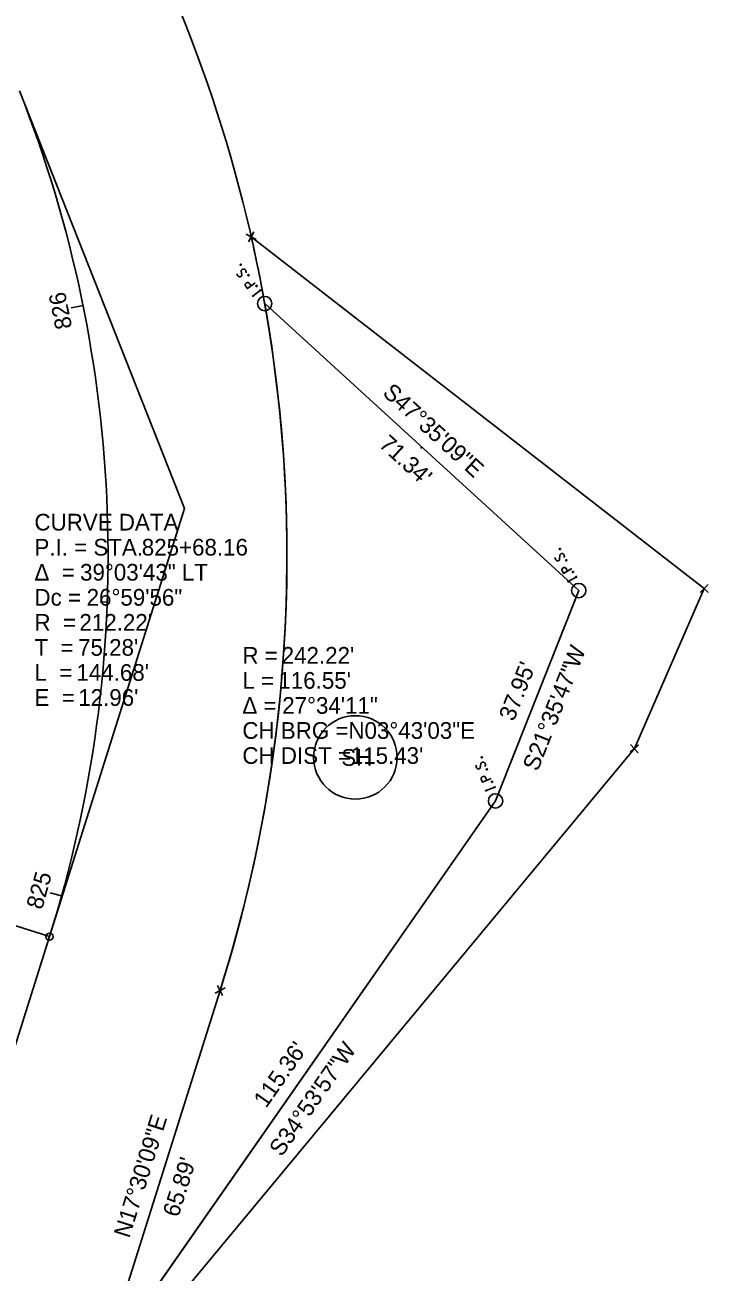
# Model space of a CAD drawing. Extents: x 2376935 to 2379466, y 252990 to 254108.
# Drawn here: x 2378019.8 to 2378134.4, y 253579.4 to 253788.5 of the extents above; entities that cross this region are included whole.
import ezdxf

# ---------------------------------------------------------------- set-up
doc = ezdxf.new("R2010")
doc.units = 0
for name, color, linetype in [('_CIVIL_CONSTRUCTION', 7, 'Continuous'), ('CM_Corridor_Key_Station', 7, 'Continuous'), ('MD_P_Special_Benching_CheckPoint', 7, 'Continuous'), ('PF_X_Ground_Line', 7, 'Continuous'), ('PV_P_Joint', 7, 'Continuous'), ('SC_Scratch1', 7, 'Continuous'), ('SC_Scratch11', 7, 'Continuous'), ('SH_Border', 7, 'Continuous'), ('SH_Cut_Line', 7, 'Continuous'), ('SH_Data', 7, 'Continuous'), ('UT_X_Electric', 7, 'Continuous'), ('UT_X_FO', 7, 'Continuous'), ('UT_X_Misc_Cells', 7, 'Continuous'), ('VG_P_Cells', 7, 'Continuous')]:
    doc.layers.add(name, color=color, linetype=linetype)

msp = doc.modelspace()

# ---------------------------------------------------------------- linework, layer by layer
at = {"layer": '_CIVIL_CONSTRUCTION'}
for p, q in [((2378029.53, 253741.45), (2378027.57, 253741.06)), ((2378033.59, 253691.73), (2378032.39, 253691.78)), ((2378025.93, 253642.44), (2378024.01, 253642.98))]:
    msp.add_line(p, q, dxfattribs=at)
at = {"layer": 'CM_Corridor_Key_Station'}
msp.add_circle((2378075.21, 253665.67), 7, dxfattribs=at)
at = {"layer": 'MD_P_Special_Benching_CheckPoint'}
for p, q in [((2378057.74, 253752.97), (2378133.68, 253693.98)), ((2378112.67, 253693.66), (2378060, 253741.78)), ((2378098.71, 253658.38), (2378112.67, 253693.66)), ((2378133.68, 253693.98), (2378122, 253667.16)), ((2378122, 253667.16), (2378030.6, 253557.09)), ((2378032.7, 253563.76), (2378098.71, 253658.38))]:
    msp.add_line(p, q, dxfattribs=at)
msp.add_arc((2377821.51, 253699.44), 242.22, 10.0673, 12.7672, dxfattribs=at)
at = {"layer": 'PF_X_Ground_Line'}
for p, q in [((2378046.78, 253788.45), (2377965.62, 253993.88)), ((2377963.22, 253343.41), (2378052.52, 253626.6))]:
    msp.add_line(p, q, dxfattribs=at)
msp.add_arc((2377821.51, 253699.44), 242.22, 342.4977, 21.5597, dxfattribs=at)
at = {"layer": 'SC_Scratch1'}
msp.add_line((2378023.91, 253635.62), (2377980.99, 253649.15), dxfattribs=at)
msp.add_circle((2378023.91, 253635.62), 0.6, dxfattribs=at)
at = {"layer": 'SC_Scratch11'}
for p, q in [((2378060, 253741.78), (2378112.67, 253693.66)), ((2378112.67, 253693.66), (2378098.71, 253658.38)), ((2378098.71, 253658.38), (2378032.7, 253563.76)), ((2378032.7, 253563.76), (2378052.52, 253626.6))]:
    msp.add_line(p, q, dxfattribs=at)
msp.add_arc((2377821.51, 253699.44), 242.22, 342.4977, 10.0673, dxfattribs=at)
at = {"layer": 'SH_Border'}
for p, q in [((2378058.57, 253752.53), (2378056.91, 253753.41)), ((2378057.3, 253752.14), (2378058.19, 253753.8)), ((2378134.35, 253693.32), (2378133.01, 253694.64)), ((2378133.02, 253693.31), (2378134.35, 253694.65)), ((2378121.3, 253666.53), (2378122.7, 253667.79)), ((2378122.64, 253666.46), (2378121.37, 253667.86)), ((2378051.68, 253626.16), (2378053.35, 253627.03)), ((2378052.95, 253625.76), (2378052.08, 253627.43))]:
    msp.add_line(p, q, dxfattribs=at)
at = {"layer": 'SH_Cut_Line'}
for points in [[(2378055.9, 253748.19), (2378055.87, 253748.24), (2378055.87, 253748.28), (2378055.89, 253748.33), (2378055.94, 253748.37), (2378056, 253748.38), (2378056.04, 253748.37), (2378056.07, 253748.32), (2378056.07, 253748.28), (2378056.05, 253748.22), (2378056, 253748.19), (2378055.94, 253748.18), (2378055.9, 253748.19)], [(2378055.38, 253746.78), (2378055.37, 253746.74), (2378055.37, 253746.7), (2378055.4, 253746.6), (2378055.45, 253746.49), (2378055.51, 253746.42), (2378055.53, 253746.39), (2378055.64, 253746.3), (2378055.78, 253746.25), (2378055.9, 253746.25), (2378056, 253746.29), (2378056.06, 253746.33), (2378056.12, 253746.41), (2378056.14, 253746.54), (2378056.08, 253747.25), (2378056.08, 253747.32), (2378056.11, 253747.37), (2378056.16, 253747.43), (2378056.22, 253747.48), (2378056.29, 253747.52), (2378056.33, 253747.54), (2378056.4, 253747.56), (2378056.45, 253747.57), (2378056.49, 253747.58), (2378056.54, 253747.57), (2378056.58, 253747.56), (2378056.63, 253747.54), (2378056.66, 253747.52), (2378056.73, 253747.45), (2378056.82, 253747.33), (2378056.86, 253747.23), (2378056.88, 253747.06), (2378056.87, 253746.95)], [(2378057.22, 253746.45), (2378057.18, 253746.49), (2378057.18, 253746.54), (2378057.2, 253746.59), (2378057.25, 253746.63), (2378057.31, 253746.63), (2378057.35, 253746.62), (2378057.39, 253746.58), (2378057.39, 253746.54), (2378057.37, 253746.48), (2378057.32, 253746.44), (2378057.26, 253746.44), (2378057.22, 253746.45)], [(2378058.38, 253745.27), (2378057.1, 253744.3), (2378056.78, 253744.73), (2378056.76, 253744.78), (2378056.73, 253744.85), (2378056.73, 253744.9), (2378056.73, 253744.94), (2378056.75, 253745.01), (2378056.78, 253745.08), (2378056.85, 253745.15), (2378056.97, 253745.24), (2378057.02, 253745.27), (2378057.09, 253745.29), (2378057.19, 253745.31), (2378057.25, 253745.3), (2378057.29, 253745.29), (2378057.34, 253745.26), (2378057.4, 253745.2), (2378057.72, 253744.77)], [(2378059.32, 253744.02), (2378058.04, 253743.05)], [(2378058.57, 253744.65), (2378058.54, 253744.7), (2378058.54, 253744.74), (2378058.56, 253744.8), (2378058.61, 253744.83), (2378058.67, 253744.84), (2378058.71, 253744.83), (2378058.74, 253744.78), (2378058.74, 253744.74), (2378058.72, 253744.68), (2378058.67, 253744.65), (2378058.61, 253744.64), (2378058.57, 253744.65)], [(2378059.42, 253743.88), (2378059.21, 253744.16)], [(2378058.15, 253742.91), (2378057.93, 253743.19)], [(2378108.73, 253699.21), (2378108.72, 253699.18), (2378108.71, 253699.13), (2378108.73, 253699.03), (2378108.77, 253698.91), (2378108.81, 253698.84), (2378108.83, 253698.81), (2378108.93, 253698.7), (2378109.06, 253698.63), (2378109.18, 253698.62), (2378109.28, 253698.65), (2378109.35, 253698.68), (2378109.42, 253698.75), (2378109.46, 253698.87), (2378109.48, 253699.59), (2378109.5, 253699.66), (2378109.53, 253699.7), (2378109.59, 253699.76), (2378109.65, 253699.8), (2378109.73, 253699.83), (2378109.77, 253699.84), (2378109.84, 253699.85), (2378109.89, 253699.86), (2378109.94, 253699.86), (2378109.99, 253699.85), (2378110.03, 253699.83), (2378110.07, 253699.81), (2378110.1, 253699.78), (2378110.16, 253699.7), (2378110.23, 253699.57), (2378110.26, 253699.47), (2378110.25, 253699.3), (2378110.23, 253699.19)], [(2378109.43, 253700.55), (2378109.4, 253700.59), (2378109.41, 253700.63), (2378109.44, 253700.69), (2378109.49, 253700.72), (2378109.55, 253700.72), (2378109.59, 253700.7), (2378109.62, 253700.65), (2378109.61, 253700.61), (2378109.58, 253700.56), (2378109.53, 253700.53), (2378109.47, 253700.53), (2378109.43, 253700.55)], [(2378110.51, 253698.65), (2378110.48, 253698.7), (2378110.49, 253698.74), (2378110.52, 253698.79), (2378110.57, 253698.82), (2378110.63, 253698.82), (2378110.67, 253698.8), (2378110.7, 253698.75), (2378110.69, 253698.71), (2378110.66, 253698.66), (2378110.61, 253698.63), (2378110.55, 253698.63), (2378110.51, 253698.65)], [(2378111.51, 253697.33), (2378110.12, 253696.54), (2378109.86, 253697), (2378109.84, 253697.05), (2378109.82, 253697.13), (2378109.83, 253697.17), (2378109.83, 253697.21), (2378109.87, 253697.28), (2378109.91, 253697.34), (2378109.98, 253697.41), (2378110.11, 253697.48), (2378110.16, 253697.5), (2378110.24, 253697.52), (2378110.34, 253697.52), (2378110.39, 253697.5), (2378110.43, 253697.49), (2378110.48, 253697.45), (2378110.53, 253697.38), (2378110.8, 253696.92)], [(2378112.28, 253695.97), (2378110.89, 253695.18)], [(2378111.62, 253696.69), (2378111.59, 253696.74), (2378111.6, 253696.78), (2378111.63, 253696.84), (2378111.68, 253696.87), (2378111.74, 253696.86), (2378111.78, 253696.85), (2378111.81, 253696.8), (2378111.8, 253696.76), (2378111.78, 253696.7), (2378111.72, 253696.67), (2378111.66, 253696.68), (2378111.62, 253696.69)], [(2378112.37, 253695.81), (2378112.19, 253696.12)], [(2378110.98, 253695.02), (2378110.8, 253695.33)], [(2378095.47, 253664.36), (2378095.45, 253664.33), (2378095.44, 253664.29), (2378095.45, 253664.19), (2378095.47, 253664.07), (2378095.5, 253663.98), (2378095.52, 253663.95), (2378095.61, 253663.84), (2378095.72, 253663.75), (2378095.85, 253663.72), (2378095.95, 253663.74), (2378096.02, 253663.77), (2378096.1, 253663.83), (2378096.15, 253663.94), (2378096.27, 253664.65), (2378096.29, 253664.72), (2378096.33, 253664.76), (2378096.39, 253664.81), (2378096.46, 253664.84), (2378096.53, 253664.85), (2378096.58, 253664.86), (2378096.65, 253664.87), (2378096.71, 253664.87), (2378096.75, 253664.86), (2378096.8, 253664.84), (2378096.83, 253664.82), (2378096.87, 253664.79), (2378096.9, 253664.77), (2378096.95, 253664.68), (2378097.01, 253664.54), (2378097.02, 253664.44), (2378096.99, 253664.27), (2378096.96, 253664.16)], [(2378096.33, 253665.61), (2378096.31, 253665.66), (2378096.32, 253665.7), (2378096.35, 253665.75), (2378096.41, 253665.77), (2378096.47, 253665.76), (2378096.51, 253665.74), (2378096.53, 253665.69), (2378096.52, 253665.65), (2378096.48, 253665.6), (2378096.43, 253665.57), (2378096.37, 253665.58), (2378096.33, 253665.61)], [(2378098, 253662.16), (2378096.52, 253661.54), (2378096.32, 253662.03), (2378096.31, 253662.09), (2378096.3, 253662.17), (2378096.31, 253662.21), (2378096.32, 253662.25), (2378096.36, 253662.31), (2378096.41, 253662.37), (2378096.49, 253662.43), (2378096.63, 253662.48), (2378096.68, 253662.49), (2378096.76, 253662.5), (2378096.86, 253662.5), (2378096.91, 253662.47), (2378096.95, 253662.45), (2378096.99, 253662.41), (2378097.04, 253662.33), (2378097.24, 253661.84)], [(2378097.17, 253663.59), (2378097.15, 253663.64), (2378097.16, 253663.68), (2378097.19, 253663.73), (2378097.25, 253663.76), (2378097.31, 253663.74), (2378097.35, 253663.72), (2378097.37, 253663.67), (2378097.36, 253663.63), (2378097.32, 253663.58), (2378097.26, 253663.56), (2378097.2, 253663.57), (2378097.17, 253663.59)], [(2378097.19, 253659.93), (2378097.05, 253660.26)], [(2378098.6, 253660.71), (2378097.12, 253660.1)], [(2378098.03, 253661.51), (2378098.01, 253661.57), (2378098.02, 253661.61), (2378098.06, 253661.66), (2378098.11, 253661.68), (2378098.17, 253661.67), (2378098.21, 253661.65), (2378098.23, 253661.6), (2378098.22, 253661.56), (2378098.19, 253661.51), (2378098.13, 253661.48), (2378098.07, 253661.49), (2378098.03, 253661.51)], [(2378098.67, 253660.55), (2378098.53, 253660.87)]]:
    msp.add_lwpolyline(points, dxfattribs=at)
for centre in [(2378060, 253741.78), (2378112.67, 253693.66), (2378098.71, 253658.38)]:
    msp.add_circle(centre, 1.2, dxfattribs=at)
at = {"layer": 'SH_Data'}
msp.add_lwpolyline([(2378032.7, 253563.76), (2378098.71, 253658.38), (2378112.67, 253693.66), (2378060, 253741.78)], dxfattribs=at)
at = {"layer": 'UT_X_Electric'}
msp.add_lwpolyline([(2378023.91, 253635.62), (2378046.55, 253707.41), (2378018.88, 253777.43)], dxfattribs=at)
at = {"layer": 'UT_X_FO'}
msp.add_line((2377935.57, 253355.49), (2378023.91, 253635.62), dxfattribs=at)
msp.add_arc((2377821.51, 253699.44), 212.22, 342.4977, 21.5597, dxfattribs=at)
at = {"layer": 'UT_X_Misc_Cells'}
msp.add_circle((2378086.27, 253717.62), 0.05, dxfattribs=at)
at = {"layer": 'VG_P_Cells'}
for p, q in [((2378133.68, 253693.98), (2378057.74, 253752.97)), ((2378122, 253667.16), (2378133.68, 253693.98)), ((2378030.6, 253557.09), (2378122, 253667.16))]:
    msp.add_line(p, q, dxfattribs=at)

# ---------------------------------------------------------------- texts
at = {"layer": '_CIVIL_CONSTRUCTION'}
for s, rotation, p in [('826', 101.4173, (2378027.73, 253737.77)), ('825', 74.4185, (2378022.66, 253640.02))]:
    msp.add_text(s, height=2.8, rotation=rotation, dxfattribs=at).set_placement(p)
at = {"layer": 'CM_Corridor_Key_Station'}
for s, rotation, p in [('S47°35\'09"E', 317.5858, (2378079.61, 253726.58)), ("71.34'", 317.5858, (2378078.99, 253717.93)), ('S21°35\'47"W', 68.4035, (2378105.78, 253663.2)), ("37.95'", 68.4035, (2378101.78, 253671.59)), ('S34°53\'57"W', 55.1008, (2378062.84, 253598.57)), ("115.36'", 55.1008, (2378060.24, 253606.74)), ('N17°30\'09"E', 72.4976, (2378037.29, 253584.94)), ("65.89'", 72.4976, (2378045.51, 253588.43))]:
    msp.add_text(s, height=2.8, rotation=rotation, dxfattribs=at).set_placement(p)
for s, p in [('R = ', (2378056.26, 253681.39)), ("242.22'", (2378062.85, 253681.39)), ('L = ', (2378056.26, 253677.19)), ("116.55'", (2378062.3, 253677.19)), ('Δ = ', (2378056.26, 253672.99)), ('27°34\'11"', (2378062.94, 253672.99)), ('CH BRG = ', (2378056.26, 253668.79)), ('N03°43\'03"E', (2378074.04, 253668.79)), ('CH DIST = ', (2378056.26, 253664.59)), ('SH', (2378072.85, 253664.27)), ("115.43'", (2378074.44, 253664.59))]:
    msp.add_text(s, height=2.8, dxfattribs=at).set_placement(p)
at = {"layer": 'PV_P_Joint'}
for s, p in [('CURVE DATA', (2378021.39, 253703.72)), ('P.I. = STA. ', (2378021.39, 253699.52)), ('825+68.16', (2378039.39, 253699.52)), ('Δ  = ', (2378021.39, 253695.32)), ('39°03\'43" LT', (2378029.04, 253695.32)), ('Dc = ', (2378021.39, 253691.12)), ('26°59\'56"', (2378030.14, 253691.12)), ('R  = ', (2378021.39, 253686.92)), ("212.22'", (2378028.93, 253686.92)), ('T  = ', (2378021.39, 253682.72)), ("75.28'", (2378028.71, 253682.72)), ('L  = ', (2378021.39, 253678.52)), ("144.68'", (2378028.43, 253678.52)), ('E  = ', (2378021.39, 253674.32)), ("12.96'", (2378028.74, 253674.32))]:
    msp.add_text(s, height=2.8, dxfattribs=at).set_placement(p)

doc.saveas('drawing.dxf')
